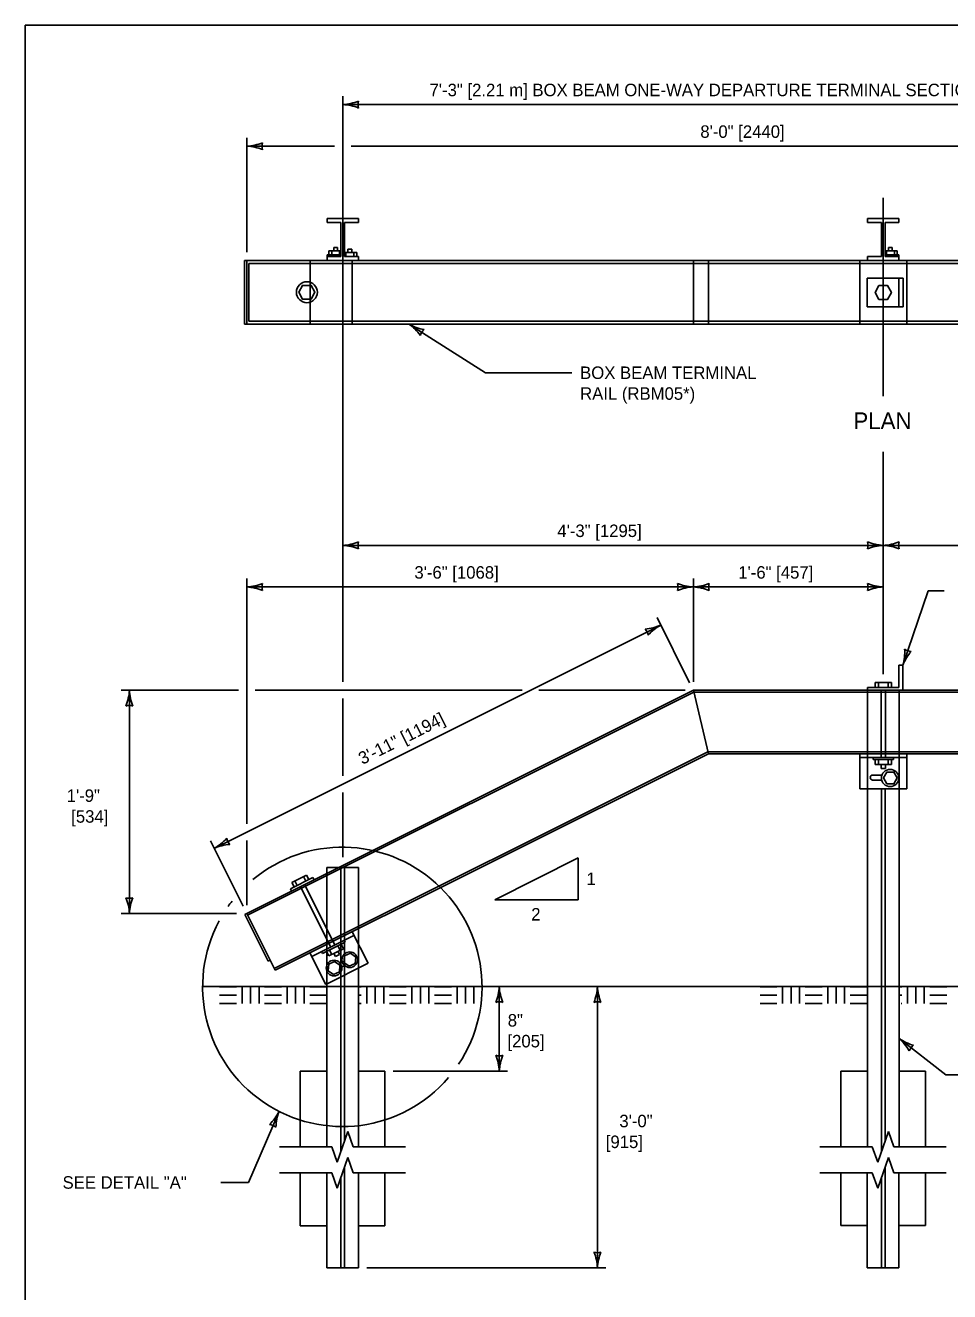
# Model space of a CAD drawing. Extents: x 49991.4 to 50021, y 49987.6 to 50011.4.
# Drawn here: x 50000.34 to 50004.78, y 50005.18 to 50011.26 of the extents above; entities that cross this region are included whole.
import ezdxf

# ---------------------------------------------------------------- set-up
doc = ezdxf.new("R2010")
doc.units = 0
for name, color, linetype in [('Level 1', 7, 'Continuous'), ('Level 2', 7, 'Continuous'), ('Level 3', 7, 'Continuous'), ('Level 4', 7, 'Continuous'), ('Level 5', 7, 'Continuous'), ('Level 6', 7, 'Continuous')]:
    doc.layers.add(name, color=color, linetype=linetype)

msp = doc.modelspace()

# ---------------------------------------------------------------- linework, layer by layer
at = {"layer": 'Level 1'}
for p, q in [((50001.7853, 50010.3162), (50001.7853, 50010.3342)), ((50001.9357, 50010.3342), (50001.7853, 50010.3342)), ((50001.8514, 50010.3162), (50001.7853, 50010.3162)), ((50001.8514, 50010.1517), (50001.8514, 50010.3162)), ((50001.8695, 50010.1517), (50001.8695, 50010.3162)), ((50001.9357, 50010.3162), (50001.8695, 50010.3162)), ((50001.9357, 50010.3162), (50001.9357, 50010.3342)), ((50004.3821, 50010.3162), (50004.3821, 50010.3342)), ((50004.3821, 50010.3342), (50004.5325, 50010.3342)), ((50004.3821, 50010.3162), (50004.4483, 50010.3162)), ((50004.4483, 50010.1517), (50004.4483, 50010.3162)), ((50004.4663, 50010.1517), (50004.4663, 50010.3162)), ((50004.4663, 50010.3162), (50004.5325, 50010.3162)), ((50004.5325, 50010.3162), (50004.5325, 50010.3342)), ((50001.3892, 50009.8274), (50001.3892, 50010.1322)), ((50006.2792, 50010.1322), (50001.3892, 50010.1322)), ((50001.3992, 50009.8274), (50001.3992, 50010.1322)), ((50001.8514, 50010.1597), (50001.7853, 50010.1597)), ((50001.7853, 50010.1322), (50001.7853, 50010.1597)), ((50001.8514, 50010.1517), (50001.7853, 50010.1517)), ((50001.7933, 50010.1597), (50001.7933, 50010.1798)), ((50001.8514, 50010.1798), (50001.7933, 50010.1798)), ((50001.8073, 50010.1597), (50001.8073, 50010.1798)), ((50001.8454, 50010.1597), (50001.8454, 50010.1798)), ((50001.8695, 50010.1718), (50001.9277, 50010.1718)), ((50001.9357, 50010.1517), (50001.8695, 50010.1517)), ((50001.8756, 50010.1517), (50001.8756, 50010.1718)), ((50001.9137, 50010.1517), (50001.9137, 50010.1718)), ((50001.9277, 50010.1517), (50001.9277, 50010.1718)), ((50001.9357, 50010.1322), (50001.9357, 50010.1517)), ((50003.5449, 50009.8274), (50003.5449, 50010.1322)), ((50004.3821, 50010.1517), (50004.4483, 50010.1517)), ((50004.3821, 50010.1322), (50004.3821, 50010.1517)), ((50004.4663, 50010.1798), (50004.5245, 50010.1798)), ((50004.4663, 50010.1597), (50004.5325, 50010.1597)), ((50004.4663, 50010.1517), (50004.5325, 50010.1517)), ((50004.4724, 50010.1597), (50004.4724, 50010.1798)), ((50004.5105, 50010.1597), (50004.5105, 50010.1798)), ((50004.5245, 50010.1597), (50004.5245, 50010.1798)), ((50004.5325, 50010.1322), (50004.5325, 50010.1597)), ((50004.3799, 50010.0486), (50004.5524, 50010.0486)), ((50004.3799, 50010.0486), (50004.3799, 50009.9102)), ((50004.5323, 50010.0486), (50004.5323, 50009.9102)), ((50004.5524, 50010.0486), (50004.5524, 50009.9102)), ((50004.3799, 50009.9102), (50004.5524, 50009.9102)), ((50006.2792, 50009.8274), (50001.3892, 50009.8274)), ((50004.5321, 50008.0817), (50004.5321, 50008.1882)), ((50004.5321, 50008.1882), (50004.5511, 50008.1882)), ((50004.5511, 50008.0682), (50004.5511, 50008.1882)), ((50003.5449, 50008.0682), (50001.3903, 50006.9909)), ((50003.5449, 50008.0682), (50003.6168, 50007.7634)), ((50006.2794, 50008.0682), (50003.5449, 50008.0682)), ((50004.3812, 50008.0817), (50004.5321, 50008.0817)), ((50004.3812, 50008.0682), (50004.3812, 50008.0817)), ((50004.4182, 50008.0817), (50004.4182, 50008.1058)), ((50004.4182, 50008.1058), (50004.4964, 50008.1058)), ((50004.4343, 50008.0817), (50004.4343, 50008.1058)), ((50004.4804, 50008.0817), (50004.4804, 50008.1058)), ((50004.4964, 50008.0817), (50004.4964, 50008.1058)), ((50003.6168, 50007.7634), (50001.5356, 50006.7228)), ((50006.2794, 50007.7634), (50003.6168, 50007.7634)), ((50004.344, 50007.5945), (50004.344, 50007.7634)), ((50004.5706, 50007.5945), (50004.5706, 50007.7634)), ((50004.5706, 50007.7449), (50004.344, 50007.7449)), ((50004.4082, 50007.7449), (50004.4082, 50007.7349)), ((50004.5064, 50007.7349), (50004.4082, 50007.7349)), ((50004.4182, 50007.7349), (50004.4182, 50007.7108)), ((50004.4964, 50007.7108), (50004.4182, 50007.7108)), ((50004.4342, 50007.7349), (50004.4342, 50007.7108)), ((50004.4803, 50007.7349), (50004.4803, 50007.7108)), ((50004.4964, 50007.7349), (50004.4964, 50007.7108)), ((50004.5064, 50007.7449), (50004.5064, 50007.7349)), ((50004.4062, 50007.6607), (50004.4511, 50007.6607)), ((50004.4062, 50007.6366), (50004.4498, 50007.6366)), ((50004.5706, 50007.5945), (50004.344, 50007.5945)), ((50004.3811, 50006.6445), (50004.3811, 50007.5945)), ((50004.5335, 50006.6445), (50004.5335, 50007.5945)), ((50001.7843, 50007.1879), (50001.7843, 50007.216)), ((50001.8404, 50007.216), (50001.7843, 50007.216)), ((50001.717, 50007.1682), (50001.609, 50007.1142)), ((50001.6864, 50007.1805), (50001.6159, 50007.1452)), ((50001.6413, 50007.1303), (50001.6303, 50007.1524)), ((50001.6831, 50007.1512), (50001.672, 50007.1733)), ((50001.6975, 50007.1584), (50001.6864, 50007.1805)), ((50001.7225, 50007.1571), (50001.717, 50007.1682)), ((50001.6145, 50007.1031), (50001.609, 50007.1142)), ((50001.6269, 50007.1231), (50001.6159, 50007.1452)), ((50001.3903, 50006.9909), (50001.5024, 50006.7667)), ((50001.3992, 50006.9954), (50001.5356, 50006.7228)), ((50001.9818, 50006.7563), (50001.9052, 50006.9076)), ((50001.9367, 50006.8454), (50001.9367, 50006.9233)), ((50001.9138, 50006.8906), (50001.7116, 50006.7895)), ((50001.8715, 50006.8574), (50001.7634, 50006.8034)), ((50001.7793, 50006.654), (50001.703, 50006.8065)), ((50001.8636, 50006.8264), (50001.7938, 50006.7915)), ((50001.5024, 50006.7667), (50001.5113, 50006.7712)), ((50001.9818, 50006.7563), (50001.7793, 50006.654)), ((50001.857, 50006.7672), (50001.8447, 50006.7604)), ((50001.8681, 50006.7462), (50001.8555, 50006.7399)), ((50001.9367, 50006.6445), (50001.9367, 50006.7335)), ((50007.21, 50006.6445), (50001.1873, 50006.6445)), ((50001.3498, 50006.6437), (50001.2686, 50006.6437)), ((50001.3498, 50006.6031), (50001.2686, 50006.6031)), ((50001.3769, 50006.5625), (50001.3769, 50006.6437)), ((50001.4175, 50006.5625), (50001.4175, 50006.6437)), ((50001.4582, 50006.5625), (50001.4582, 50006.6437)), ((50001.5665, 50006.6437), (50001.4853, 50006.6437)), ((50001.5665, 50006.6031), (50001.4853, 50006.6031)), ((50001.5936, 50006.5625), (50001.5936, 50006.6437)), ((50001.6342, 50006.5625), (50001.6342, 50006.6437)), ((50001.6748, 50006.5625), (50001.6748, 50006.6437)), ((50001.7843, 50006.6436), (50001.7021, 50006.6436)), ((50001.7843, 50006.603), (50001.7021, 50006.603)), ((50001.7843, 50006.6445), (50001.7843, 50006.6565)), ((50001.9762, 50006.5625), (50001.9762, 50006.6437)), ((50002.0168, 50006.5625), (50002.0168, 50006.6437)), ((50002.0574, 50006.5625), (50002.0574, 50006.6437)), ((50002.1658, 50006.6437), (50002.0845, 50006.6437)), ((50002.1658, 50006.6031), (50002.0845, 50006.6031)), ((50002.1929, 50006.5625), (50002.1929, 50006.6437)), ((50002.2335, 50006.5625), (50002.2335, 50006.6437)), ((50002.2741, 50006.5625), (50002.2741, 50006.6437)), ((50002.3825, 50006.6437), (50002.3012, 50006.6437)), ((50002.3825, 50006.6031), (50002.3012, 50006.6031)), ((50002.4096, 50006.5625), (50002.4096, 50006.6437)), ((50002.4502, 50006.5625), (50002.4502, 50006.6437)), ((50002.4908, 50006.5625), (50002.4908, 50006.6437)), ((50003.9466, 50006.6437), (50003.8654, 50006.6437)), ((50003.9466, 50006.6031), (50003.8654, 50006.6031)), ((50003.9737, 50006.5625), (50003.9737, 50006.6437)), ((50004.0143, 50006.5625), (50004.0143, 50006.6437)), ((50004.055, 50006.5625), (50004.055, 50006.6437)), ((50004.1633, 50006.6437), (50004.0821, 50006.6437)), ((50004.1633, 50006.6031), (50004.0821, 50006.6031)), ((50004.1904, 50006.5625), (50004.1904, 50006.6437)), ((50004.231, 50006.5625), (50004.231, 50006.6437)), ((50004.2716, 50006.5625), (50004.2716, 50006.6437)), ((50004.38, 50006.6437), (50004.2988, 50006.6437)), ((50004.38, 50006.6031), (50004.2988, 50006.6031)), ((50004.38, 50006.6437), (50004.38, 50006.6437)), ((50004.573, 50006.5625), (50004.573, 50006.6437)), ((50004.6136, 50006.5625), (50004.6136, 50006.6437)), ((50004.6542, 50006.5625), (50004.6542, 50006.6437)), ((50004.7626, 50006.6437), (50004.6813, 50006.6437)), ((50004.7626, 50006.6031), (50004.6813, 50006.6031)), ((50001.3498, 50006.5625), (50001.2686, 50006.5625)), ((50001.5665, 50006.5625), (50001.4853, 50006.5625)), ((50001.7843, 50006.5624), (50001.7021, 50006.5624)), ((50002.1658, 50006.5625), (50002.0845, 50006.5625)), ((50002.3825, 50006.5625), (50002.3012, 50006.5625)), ((50003.9466, 50006.5625), (50003.8654, 50006.5625)), ((50004.1633, 50006.5625), (50004.0821, 50006.5625)), ((50004.38, 50006.5625), (50004.2988, 50006.5625)), ((50004.7626, 50006.5625), (50004.6813, 50006.5625))]:
    msp.add_line(p, q, dxfattribs=at)
for points in [[(50008.6146, 50011.2628), (50000.3356, 50011.2628), (50000.3356, 50000.0624), (50008.6146, 50000.0624)], [(50001.7091, 50009.9472), (50001.667, 50009.9472), (50001.6489, 50009.9813), (50001.667, 50010.0134), (50001.7091, 50010.0134), (50001.7271, 50009.9813)], [(50004.4361, 50010.0125), (50004.4782, 50010.0125), (50004.4962, 50009.9784), (50004.4782, 50009.9463), (50004.4361, 50009.9463), (50004.418, 50009.9784)], [(50004.4744, 50007.6186), (50004.5084, 50007.6186), (50004.5245, 50007.6466), (50004.5084, 50007.6747), (50004.4744, 50007.6747), (50004.4583, 50007.6466)], [(50001.9227, 50006.7865), (50001.8972, 50006.8047), (50001.8687, 50006.7916), (50001.8657, 50006.7604), (50001.8912, 50006.7423), (50001.9197, 50006.7553)], [(50001.847, 50006.7466), (50001.8215, 50006.7648), (50001.793, 50006.7517), (50001.79, 50006.7206), (50001.8156, 50006.7024), (50001.8441, 50006.7154)]]:
    msp.add_lwpolyline(points, close=True, dxfattribs=at)
for points in [[(50001.8174, 50010.1798), (50001.8174, 50010.1958)], [(50001.8354, 50010.1958), (50001.8174, 50010.1958)], [(50001.8354, 50010.1798), (50001.8354, 50010.1958)], [(50004.4824, 50010.1798), (50004.4824, 50010.1958)], [(50004.4824, 50010.1958), (50004.5004, 50010.1958)], [(50004.5004, 50010.1798), (50004.5004, 50010.1958)], [(50001.8856, 50010.1718), (50001.8856, 50010.1878)], [(50001.8856, 50010.1878), (50001.9036, 50010.1878)], [(50001.9036, 50010.1718), (50001.9036, 50010.1878)], [(50004.4463, 50007.7108), (50004.4463, 50007.6928)], [(50004.4683, 50007.7108), (50004.4683, 50007.6928)], [(50004.4683, 50007.6928), (50004.4463, 50007.6928)], [(50001.8528, 50006.848), (50001.8636, 50006.8264)], [(50001.8667, 50006.867), (50001.8715, 50006.8574)], [(50001.7586, 50006.813), (50001.7634, 50006.8034)], [(50001.7829, 50006.8131), (50001.7938, 50006.7915)], [(50001.7967, 50006.82), (50001.8074, 50006.7983)], [(50001.8178, 50006.8035), (50001.8254, 50006.7884)], [(50001.8454, 50006.7984), (50001.8254, 50006.7884)], [(50001.8375, 50006.8404), (50001.8483, 50006.8188)], [(50001.8379, 50006.8136), (50001.8454, 50006.7984)], [(50001.9492, 50006.6436), (50001.9367, 50006.6436)], [(50001.9492, 50006.603), (50001.9367, 50006.603)], [(50004.5459, 50006.6437), (50004.5348, 50006.6437)], [(50004.5459, 50006.6031), (50004.5386, 50006.6031)], [(50001.9492, 50006.5624), (50001.9367, 50006.5624)], [(50004.5459, 50006.5625), (50004.5424, 50006.5625)]]:
    msp.add_lwpolyline(points, dxfattribs=at)
for centre, radius in [((50001.6881, 50009.9804), 0.0503), ((50004.4901, 50007.6465), 0.0415), ((50001.8941, 50006.7733), 0.0376), ((50001.8185, 50006.7334), 0.0376)]:
    msp.add_circle(centre, radius, dxfattribs=at)
msp.add_arc((50004.4062, 50007.6487), 0.012, 90, 270, dxfattribs=at)
at = {"layer": 'Level 3'}
for p, q in [((50006.2921, 50010.8823), (50001.8605, 50010.8823)), ((50001.3992, 50010.1722), (50001.3992, 50010.7222)), ((50001.3992, 50010.6822), (50001.8205, 50010.6822)), ((50001.9005, 50010.6822), (50006.2921, 50010.6822)), ((50002.5466, 50009.5937), (50002.1783, 50009.8274)), ((50002.5466, 50009.5937), (50002.9608, 50009.5937)), ((50001.8605, 50008.7643), (50004.4573, 50008.7643)), ((50004.4573, 50008.7643), (50006.2921, 50008.7643)), ((50001.3992, 50007.4267), (50001.3992, 50008.6043)), ((50003.5449, 50008.5643), (50001.3992, 50008.5643)), ((50003.5449, 50008.1082), (50003.5449, 50008.6043)), ((50003.5449, 50008.5643), (50004.4573, 50008.5643)), ((50004.5511, 50008.1882), (50004.6728, 50008.546)), ((50004.6728, 50008.546), (50004.7505, 50008.546)), ((50003.3884, 50008.3813), (50001.2427, 50007.3084)), ((50003.527, 50008.104), (50003.3705, 50008.417)), ((50001.3592, 50008.0682), (50000.7956, 50008.0682)), ((50000.8356, 50008.0682), (50000.8356, 50006.9954)), ((50002.7223, 50008.0682), (50001.4392, 50008.0682)), ((50003.5049, 50008.0682), (50002.8023, 50008.0682)), ((50001.3813, 50007.0312), (50001.2248, 50007.3442)), ((50001.3992, 50007.0354), (50001.3992, 50007.3467)), ((50002.9915, 50007.2625), (50002.5905, 50007.0619)), ((50002.9915, 50007.0619), (50002.9915, 50007.2625)), ((50002.9915, 50007.0619), (50002.5905, 50007.0619)), ((50001.3503, 50006.9954), (50000.7956, 50006.9954)), ((50002.6126, 50006.2383), (50002.6126, 50006.6445)), ((50003.0841, 50005.2926), (50003.0841, 50006.6445)), ((50002.1025, 50006.2383), (50002.6526, 50006.2383)), ((50001.4076, 50005.7033), (50001.5543, 50006.0447)), ((50001.2749, 50005.7033), (50001.4076, 50005.7033)), ((50001.9766, 50005.2926), (50003.1241, 50005.2926))]:
    msp.add_line(p, q, dxfattribs=at)
msp.add_lwpolyline([(50004.8762, 50006.2205), (50004.7585, 50006.2205), (50004.5324, 50006.3959)], dxfattribs=at)
for centre, radius, start, end in [((50001.8513, 50011.1044), 0.2223, 272.36048, 292.54399), ((50001.849, 50010.6495), 0.233, 67.92284, 87.17269), ((50001.9887, 50010.8823), 0.0548, 162.13882, 197.86118), ((50001.3901, 50010.9043), 0.2223, 272.36048, 292.54399), ((50001.3877, 50010.4495), 0.233, 67.92284, 87.17269), ((50001.5274, 50010.6822), 0.0548, 162.13882, 197.86118), ((50002.2896, 50010.0199), 0.2223, 239.96143, 260.14494), ((50002.0439, 50009.6371), 0.233, 35.52379, 54.77364), ((50002.2866, 50009.7587), 0.0548, 129.73977, 165.46213), ((50001.8513, 50008.9864), 0.2223, 272.36048, 292.54399), ((50001.849, 50008.5316), 0.233, 67.92284, 87.17269), ((50001.9887, 50008.7643), 0.0548, 162.13882, 197.86118), ((50004.3291, 50008.7643), 0.0548, 342.13882, 17.86118), ((50004.4688, 50008.997), 0.233, 247.92284, 267.17269), ((50004.4664, 50008.5422), 0.2223, 92.36048, 112.54399), ((50004.4481, 50008.9864), 0.2223, 272.36048, 292.54399), ((50004.4458, 50008.5316), 0.233, 67.92284, 87.17269), ((50004.5855, 50008.7643), 0.0548, 162.13882, 197.86118), ((50001.3901, 50008.7864), 0.2223, 272.36048, 292.54399), ((50001.3878, 50008.3316), 0.233, 67.92284, 87.17269), ((50001.5275, 50008.5643), 0.0548, 162.13882, 197.86118), ((50003.4167, 50008.5643), 0.0548, 342.13882, 17.86118), ((50003.5564, 50008.797), 0.233, 247.92284, 267.17269), ((50003.554, 50008.3422), 0.2223, 92.36048, 112.54399), ((50003.5357, 50008.7864), 0.2223, 272.36048, 292.54399), ((50003.5334, 50008.3316), 0.233, 67.92284, 87.17269), ((50003.6731, 50008.5643), 0.0548, 162.13882, 197.86118), ((50004.3291, 50008.5643), 0.0548, 342.13882, 17.86118), ((50004.4688, 50008.797), 0.233, 247.92284, 267.17269), ((50004.4664, 50008.3422), 0.2223, 92.36048, 112.54399), ((50003.2946, 50008.5946), 0.233, 274.48789, 293.73774), ((50003.4959, 50008.1867), 0.2223, 118.92553, 139.10904), ((50003.2737, 50008.3239), 0.0548, 8.70387, 44.42623), ((50004.3271, 50008.2522), 0.233, 344.04261, 3.29246), ((50004.7585, 50008.108), 0.2223, 138.67131, 158.85482), ((50004.5924, 50008.3095), 0.0548, 233.35412, 269.07648), ((50000.6028, 50008.0797), 0.233, 337.92284, 357.17269), ((50001.0577, 50008.0774), 0.2223, 182.36048, 202.54399), ((50000.8356, 50007.94), 0.0548, 72.13882, 107.86118), ((50001.1352, 50007.503), 0.2223, 298.92553, 319.10904), ((50001.3574, 50007.3658), 0.0548, 188.70387, 224.42623), ((50001.3365, 50007.0952), 0.233, 94.48789, 113.73774), ((50001.8584, 50006.643), 0.6711, 326.32931, 129.75178), ((50000.6134, 50006.9863), 0.2223, 2.36048, 22.54399), ((50000.8356, 50007.1236), 0.0548, 252.13882, 287.86118), ((50001.0683, 50006.9839), 0.233, 157.92284, 177.17269), ((50001.8584, 50006.643), 0.6711, 142.1338, 144.90298), ((50001.8584, 50006.643), 0.6711, 151.7343, 319.498), ((50002.3799, 50006.656), 0.233, 337.92284, 357.17269), ((50002.8347, 50006.6536), 0.2223, 182.36048, 202.54399), ((50002.8514, 50006.656), 0.233, 337.92284, 357.17269), ((50003.3063, 50006.6536), 0.2223, 182.36048, 202.54399), ((50002.6126, 50006.5163), 0.0548, 72.13882, 107.86118), ((50003.0841, 50006.5163), 0.0548, 72.13882, 107.86118), ((50004.6613, 50006.577), 0.2223, 234.55685, 254.74036), ((50004.3807, 50006.219), 0.233, 30.11921, 49.36906), ((50004.6337, 50006.3173), 0.0548, 124.33519, 160.05755), ((50002.3904, 50006.2291), 0.2223, 2.36048, 22.54399), ((50002.6126, 50006.3665), 0.0548, 252.13882, 287.86118), ((50002.8453, 50006.2268), 0.233, 157.92284, 177.17269), ((50001.345, 50006.1472), 0.233, 314.66967, 333.91952), ((50001.762, 50005.9655), 0.2223, 159.10731, 179.29082), ((50001.5037, 50005.9269), 0.0548, 48.88565, 84.60801), ((50002.862, 50005.2834), 0.2223, 2.36048, 22.54399), ((50003.0841, 50005.4208), 0.0548, 252.13882, 287.86118), ((50003.3169, 50005.2811), 0.233, 157.92284, 177.17269)]:
    msp.add_arc(centre, radius, start, end, dxfattribs=at)
at = {"layer": 'Level 4'}
for p, q in [((50001.7032, 50009.8274), (50001.7032, 50010.1322)), ((50001.9052, 50009.8274), (50001.9052, 50010.1322)), ((50003.6171, 50009.8274), (50003.6171, 50010.1322)), ((50004.3441, 50009.8274), (50004.3441, 50010.1322)), ((50004.5707, 50009.8274), (50004.5707, 50010.1322)), ((50001.4089, 50009.8416), (50001.4089, 50010.1189)), ((50006.2792, 50010.1189), (50001.4089, 50010.1189)), ((50006.2792, 50009.8416), (50001.4089, 50009.8416)), ((50004.3811, 50007.5945), (50004.3811, 50008.0682)), ((50004.4464, 50007.7449), (50004.4464, 50008.0682)), ((50004.4684, 50007.7449), (50004.4684, 50008.0682)), ((50004.5335, 50007.5945), (50004.5335, 50008.0682)), ((50003.5472, 50008.0586), (50001.4036, 50006.9868)), ((50006.2794, 50008.0586), (50003.5472, 50008.0586)), ((50003.6146, 50007.773), (50001.5313, 50006.7314)), ((50006.2794, 50007.773), (50003.6146, 50007.773)), ((50004.4488, 50005.8534), (50004.4488, 50007.5945)), ((50004.4658, 50005.9015), (50004.4658, 50007.5945)), ((50001.9367, 50007.216), (50001.8404, 50007.216)), ((50001.8519, 50005.8533), (50001.8519, 50007.216)), ((50001.869, 50005.9014), (50001.869, 50007.216)), ((50001.9367, 50006.9233), (50001.9367, 50007.216)), ((50001.7843, 50006.6565), (50001.7843, 50007.1879)), ((50001.8022, 50006.8348), (50001.6574, 50007.1245)), ((50001.8222, 50006.8448), (50001.6774, 50007.1345)), ((50001.9367, 50006.7335), (50001.9367, 50006.8454)), ((50001.7843, 50006.6445), (50001.7843, 50005.8744)), ((50001.9366, 50006.6445), (50001.9366, 50005.8744)), ((50004.3811, 50006.6445), (50004.3811, 50005.8744)), ((50004.5335, 50006.6445), (50004.5335, 50005.8744)), ((50001.6563, 50006.2383), (50001.6563, 50005.8744)), ((50001.7843, 50006.2383), (50001.6563, 50006.2383)), ((50002.0625, 50006.2383), (50001.9366, 50006.2383)), ((50002.0625, 50006.2383), (50002.0625, 50005.8744)), ((50004.38, 50006.2384), (50004.2531, 50006.2384)), ((50004.2531, 50006.2384), (50004.2531, 50005.8744)), ((50004.6593, 50006.2384), (50004.5324, 50006.2384)), ((50004.6593, 50006.2384), (50004.6593, 50005.8744)), ((50001.6563, 50005.7497), (50001.6563, 50005.4957)), ((50001.7842, 50005.7497), (50001.7842, 50005.2926)), ((50001.869, 50005.2926), (50001.869, 50005.7767)), ((50001.9366, 50005.7497), (50001.9366, 50005.2926)), ((50002.0625, 50005.7497), (50002.0625, 50005.4957)), ((50004.2531, 50005.7497), (50004.2531, 50005.4958)), ((50004.38, 50005.7497), (50004.38, 50005.2927)), ((50004.4658, 50005.2927), (50004.4658, 50005.7768)), ((50004.5324, 50005.7497), (50004.5324, 50005.2927)), ((50004.6593, 50005.7497), (50004.6593, 50005.4958)), ((50001.8519, 50005.2926), (50001.8519, 50005.7286)), ((50004.4488, 50005.2927), (50004.4488, 50005.7287)), ((50001.7842, 50005.4957), (50001.6563, 50005.4957)), ((50002.0625, 50005.4957), (50001.9366, 50005.4957)), ((50004.38, 50005.4958), (50004.2531, 50005.4958)), ((50004.6593, 50005.4958), (50004.5324, 50005.4958)), ((50001.9366, 50005.2926), (50001.7842, 50005.2926)), ((50004.5324, 50005.2927), (50004.38, 50005.2927))]:
    msp.add_line(p, q, dxfattribs=at)
at = {"layer": 'Level 5'}
for p, q in [((50001.8605, 50010.9223), (50001.8605, 50008.1082)), ((50004.4573, 50010.4342), (50004.4573, 50009.4811)), ((50004.4573, 50009.213), (50004.4573, 50008.1458)), ((50001.8605, 50008.0282), (50001.8605, 50007.6573)), ((50001.8605, 50007.5773), (50001.8605, 50007.266))]:
    msp.add_line(p, q, dxfattribs=at)
at = {"layer": 'Level 6'}
for p, q in [((50001.8853, 50005.9475), (50001.8594, 50005.8744)), ((50001.8853, 50005.9475), (50001.9112, 50005.8744)), ((50004.4821, 50005.9475), (50004.4562, 50005.8744)), ((50004.4821, 50005.9475), (50004.508, 50005.8744)), ((50001.8076, 50005.8744), (50001.5563, 50005.8744)), ((50001.8076, 50005.8744), (50001.8335, 50005.8013)), ((50001.8594, 50005.8744), (50001.8335, 50005.8013)), ((50002.1625, 50005.8744), (50001.9112, 50005.8744)), ((50004.4044, 50005.8744), (50004.1531, 50005.8744)), ((50004.4044, 50005.8744), (50004.4303, 50005.8013)), ((50004.4562, 50005.8744), (50004.4303, 50005.8013)), ((50004.7593, 50005.8744), (50004.508, 50005.8744)), ((50001.8853, 50005.8228), (50001.8594, 50005.7497)), ((50001.8853, 50005.8228), (50001.9112, 50005.7497)), ((50004.4821, 50005.8228), (50004.4562, 50005.7497)), ((50004.4821, 50005.8228), (50004.508, 50005.7497)), ((50001.5563, 50005.7497), (50001.8076, 50005.7497)), ((50001.8076, 50005.7497), (50001.8335, 50005.6766)), ((50001.8594, 50005.7497), (50001.8335, 50005.6766)), ((50001.9112, 50005.7497), (50002.1625, 50005.7497)), ((50004.1531, 50005.7497), (50004.4044, 50005.7497)), ((50004.4044, 50005.7497), (50004.4303, 50005.6766)), ((50004.4562, 50005.7497), (50004.4303, 50005.6766)), ((50004.508, 50005.7497), (50004.7593, 50005.7497))]:
    msp.add_line(p, q, dxfattribs=at)

# ---------------------------------------------------------------- texts
at = {"layer": 'Level 2'}
for s, height, p in [('7\'-3" [2.21 m] BOX BEAM ONE-WAY DEPARTURE TERMINAL SECTION PAY LIMITS', 0.06, (50002.2775, 50010.9223)), ('8\'-0" [2440]', 0.06, (50003.5783, 50010.7222)), ('BOX BEAM TERMINAL', 0.06, (50003.0008, 50009.5637)), ('RAIL (RBM05*)', 0.06, (50003.0008, 50009.4637)), ('PLAN', 0.08, (50004.3136, 50009.323)), ('4\'-3" [1295]', 0.06, (50002.8915, 50008.8043)), ('3\'-6" [1068]', 0.06, (50002.2047, 50008.6043)), ('1\'-6" [457]', 0.06, (50003.7606, 50008.6043)), ('1\'-9"', 0.06, (50000.5343, 50007.5318)), ('[534]', 0.06, (50000.556, 50007.4318)), ('1 ', 0.06, (50003.0315, 50007.1323)), ('2', 0.06, (50002.766, 50006.9619)), ('8"', 0.06, (50002.6531, 50006.4523)), ('[205]', 0.06, (50002.6517, 50006.3523)), ('3\'-0"', 0.06, (50003.1894, 50005.9685)), ('[915]', 0.06, (50003.1241, 50005.8685)), (' SEE DETAIL "A"', 0.06, (50000.4922, 50005.6733))]:
    msp.add_text(s, height=height, dxfattribs=at).set_placement(p)
msp.add_text('3\'-11" [1194]', height=0.06, rotation=26.56505, dxfattribs=at).set_placement((50001.9549, 50007.7092))

doc.saveas('drawing.dxf')
